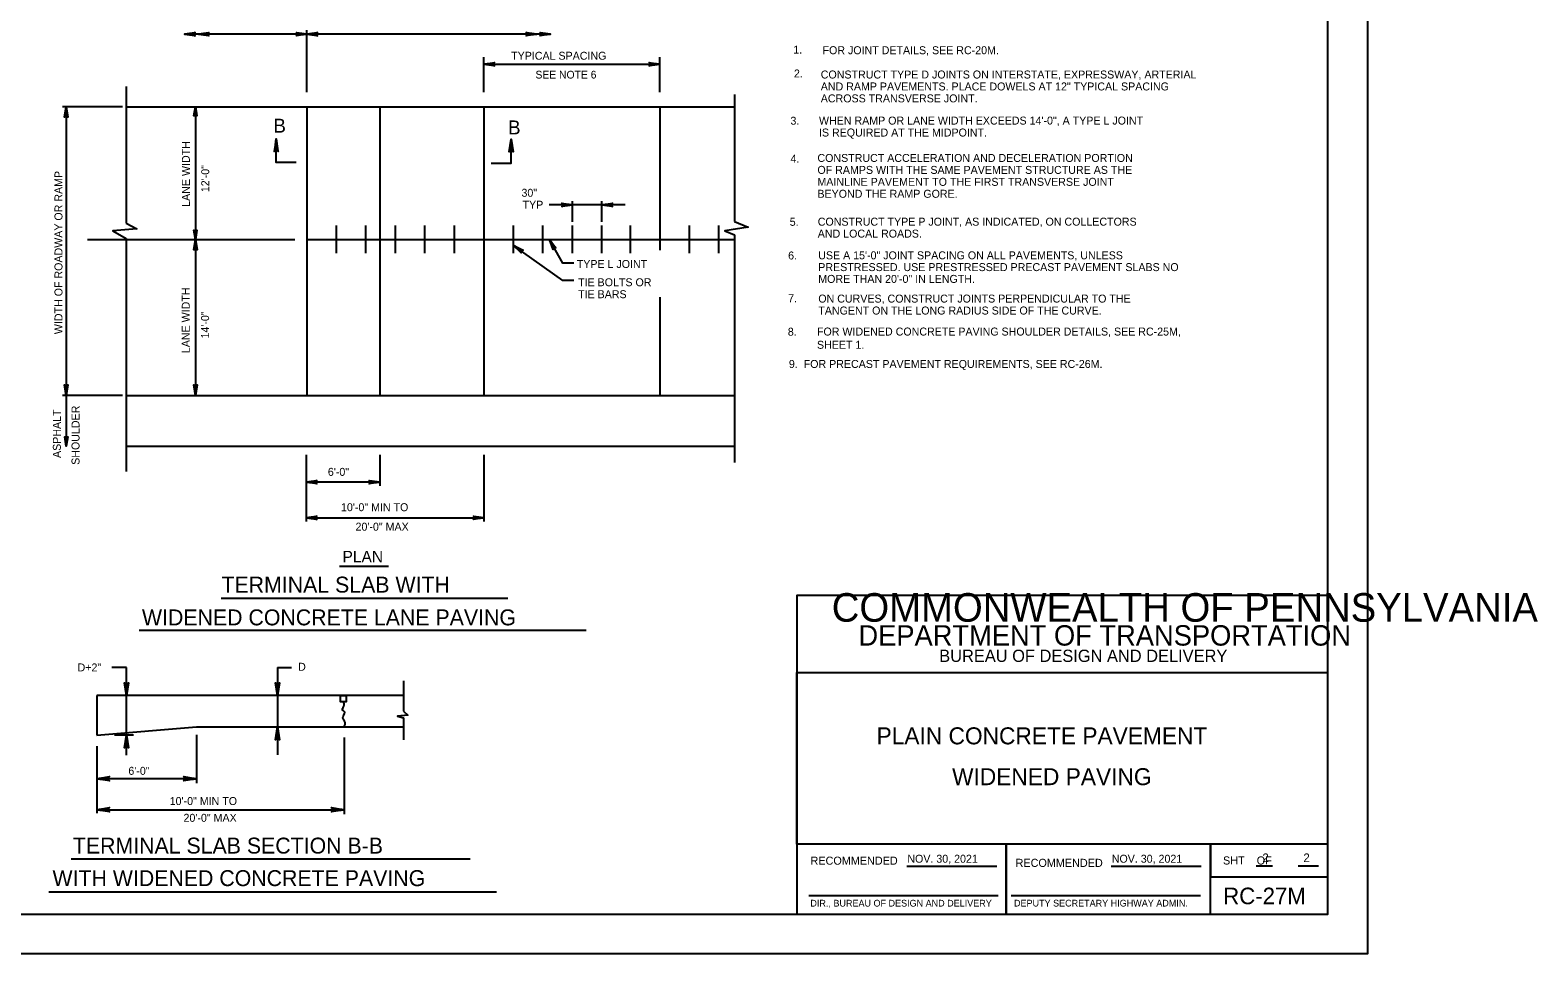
# Model space of a CAD drawing. Extents: x 637877 to 639321, y 297902 to 299090.
# Drawn here: x 638753 to 639321, y 297902 to 298250 of the extents above; entities that cross this region are included whole.
import ezdxf

# ---------------------------------------------------------------- set-up
doc = ezdxf.new("R2010")
doc.units = 0
for name, color, linetype in [('1', 7, 'Continuous'), ('2', 7, 'Continuous'), ('3', 7, 'Continuous'), ('PLT-BNDY', 7, 'Continuous')]:
    doc.layers.add(name, color=color, linetype=linetype)

msp = doc.modelspace()

# ---------------------------------------------------------------- linework, layer by layer
at = {"layer": '1'}
for p, q in [((639082.98, 297934.56), (639116.87, 297934.56)), ((639159.98, 297934.56), (639193.85, 297934.56)), ((639214.52, 297934.78), (639220.66, 297934.78)), ((639230.33, 297934.78), (639237.98, 297934.78)), ((639046.06, 297923.52), (639117.31, 297923.52)), ((639122.23, 297923.52), (639193.57, 297923.52))]:
    msp.add_line(p, q, dxfattribs=at)
for points in [[(639241.51, 297916.57), (639241.51, 298480.57), (638455.51, 298480.57), (638455.51, 297916.57), (639241.51, 297916.57), (639241.51, 297942.93), (639041.51, 297942.93), (639041.51, 298007.61), (639241.51, 298007.61), (639241.51, 298036.57), (639041.51, 298036.57), (639041.51, 297916.57), (639120.32, 297916.57), (639120.32, 297942.93), (639120.32, 297916.57), (639197.32, 297916.57), (639197.32, 297942.93), (639197.32, 297930.61), (639241.51, 297930.61)], [(638814.58, 298217.46), (638814.82, 298217.58), (638815, 298220.77), (638814.58, 298217.46), (638814.44, 298217.29), (638815, 298220.77), (638815.16, 298217.58), (638815.39, 298217.47), (638815, 298220.77), (638815.55, 298217.29), (638815.39, 298217.47)], [(638815.41, 298174.08), (638815.17, 298173.96), (638815, 298170.77), (638815.41, 298174.08), (638815.56, 298174.25), (638815, 298170.77), (638814.84, 298173.96), (638814.6, 298174.07), (638815, 298170.77), (638814.45, 298174.25), (638814.6, 298174.07)], [(638766.76, 298096.15), (638766.52, 298096.03), (638766.35, 298092.84), (638766.76, 298096.15), (638766.91, 298096.32), (638766.35, 298092.84), (638766.19, 298096.02), (638765.95, 298096.14), (638766.35, 298092.84), (638765.79, 298096.32), (638765.95, 298096.14)]]:
    msp.add_lwpolyline(points, dxfattribs=at)
msp.add_lwpolyline([(638869.69, 297998.93), (638871.78, 297998.93), (638871.78, 297996.49), (638869.69, 297996.49)], close=True, dxfattribs=at)
msp.add_spline([(638870.97, 297987.06), (638871.38, 297988.78), (638870.47, 297990.44), (638871.21, 297992.59), (638870.39, 297993.58), (638871.05, 297995.4), (638870.72, 297996.48)], degree=3, dxfattribs=at)
at = {"layer": '2'}
for p, q in [((638857, 298226.22), (638857, 298249.58)), ((638857, 298226.22), (638857, 298249.58)), ((638857, 298248.12), (638810.91, 298248.12)), ((638857, 298248.12), (638840.89, 298248.12)), ((638948.76, 298248.12), (638857, 298248.12)), ((638897.71, 298248.12), (638857, 298248.12)), ((638923.66, 298226.22), (638923.66, 298239.44)), ((638989.94, 298226.22), (638989.94, 298239.44)), ((638923.66, 298236.75), (638989.94, 298236.75)), ((638788.94, 298228.42), (638788.94, 298176.85)), ((638787.48, 298220.77), (638764.89, 298220.77)), ((638766.35, 298220.77), (638766.35, 298096.37)), ((638788.94, 298220.77), (639018.1, 298220.77)), ((638815, 298220.77), (638815, 298170.77)), ((638855.68, 298220.77), (638918.21, 298220.77)), ((638857, 298220.95), (638857, 298111.95)), ((638884.4, 298220.95), (638884.4, 298111.95)), ((638923.66, 298220.95), (638923.66, 298111.95)), ((638989.94, 298220.95), (638989.94, 298166.71)), ((639018.1, 298225.37), (639018.1, 298177.47)), ((638968.1, 298183.75), (638948.24, 298183.75)), ((638956.99, 298177.44), (638956.99, 298185.21)), ((638968.1, 298177.44), (638968.1, 298185.21)), ((638976.85, 298183.75), (638968.1, 298183.75)), ((638774.4, 298170.77), (638852.49, 298170.77)), ((638788.94, 298171.05), (638788.94, 298083.37)), ((638815, 298170.77), (638815, 298111.95)), ((638815, 298170.77), (638815, 298170.77)), ((638857, 298170.77), (639017.72, 298170.77)), ((638868.11, 298170.77), (638868.11, 298170.77)), ((638923.66, 298170.77), (638923.66, 298170.77)), ((639018.1, 298172.44), (639018.1, 298086.68)), ((638989.94, 298148.95), (638989.94, 298111.95)), ((638787.48, 298111.95), (638764.89, 298111.95)), ((638788.94, 298111.95), (639018.1, 298111.95)), ((638788.94, 298092.84), (639018.1, 298092.84)), ((638790.4, 298092.84), (638801.81, 298092.84)), ((638856.72, 298089.61), (638856.72, 298077.89)), ((638856.72, 298089.61), (638856.72, 298064.44)), ((638884.4, 298089.61), (638884.4, 298077.89)), ((638923.66, 298089.61), (638923.66, 298064.44)), ((638884.4, 298079.35), (638856.72, 298079.35)), ((638856.72, 298065.9), (638923.66, 298065.9)), ((638789.06, 298009.42), (638783.45, 298009.42)), ((638789.06, 297983.92), (638789.06, 298009.42)), ((638845.93, 298009.42), (638845.93, 297998.92)), ((638893.36, 298004.45), (638893.36, 297992.97)), ((638870.84, 297998.92), (638777.84, 297998.92)), ((638777.84, 297998.92), (638777.84, 297983.92)), ((638893.36, 297998.92), (638870.84, 297998.92)), ((638777.84, 297983.92), (638815.34, 297987.05)), ((638815.34, 297987.05), (638893.36, 297987.05)), ((638893.36, 297990.44), (638893.36, 297982.22)), ((638791.61, 297983.92), (638784.49, 297983.92)), ((638789.06, 297976.39), (638789.06, 297983.92)), ((638815.34, 297984.14), (638815.34, 297965.83)), ((638870.97, 297983.03), (638870.97, 297954.15)), ((638777.84, 297979.84), (638777.84, 297954.63)), ((638815.34, 297967.58), (638777.84, 297967.58)), ((638777.84, 297955.9), (638870.97, 297955.9))]:
    msp.add_line(p, q, dxfattribs=at)
for points in [[(638814.7, 298247.64), (638814.56, 298247.92), (638810.91, 298248.12), (638814.7, 298247.64), (638814.89, 298247.47), (638810.91, 298248.12), (638814.56, 298248.3), (638814.69, 298248.57), (638810.91, 298248.12), (638814.89, 298248.75), (638814.69, 298248.57)], [(638819.91, 298247.64), (638819.77, 298247.92), (638816.12, 298248.12), (638819.91, 298247.64), (638820.1, 298247.47), (638816.12, 298248.12), (638819.76, 298248.3), (638819.9, 298248.57), (638816.12, 298248.12), (638820.1, 298248.75), (638819.9, 298248.57)], [(638853.21, 298248.59), (638853.35, 298248.32), (638857, 298248.12), (638853.21, 298248.59), (638853.02, 298248.76), (638857, 298248.12), (638853.36, 298247.94), (638853.22, 298247.67), (638857, 298248.12), (638853.02, 298247.49), (638853.22, 298247.67)], [(638860.78, 298247.64), (638860.64, 298247.92), (638857, 298248.12), (638860.78, 298247.64), (638860.97, 298247.47), (638857, 298248.12), (638860.64, 298248.3), (638860.77, 298248.57), (638857, 298248.12), (638860.97, 298248.75), (638860.77, 298248.57)], [(638939.77, 298248.59), (638939.91, 298248.32), (638943.56, 298248.12), (638939.77, 298248.59), (638939.58, 298248.76), (638943.56, 298248.12), (638939.92, 298247.94), (638939.78, 298247.67), (638943.56, 298248.12), (638939.58, 298247.49), (638939.78, 298247.67)], [(638944.98, 298248.59), (638945.12, 298248.32), (638948.76, 298248.12), (638944.98, 298248.59), (638944.79, 298248.76), (638948.76, 298248.12), (638945.12, 298247.94), (638944.99, 298247.67), (638948.76, 298248.12), (638944.79, 298247.49), (638944.99, 298247.67)], [(638927.44, 298236.28), (638927.3, 298236.55), (638923.66, 298236.75), (638927.44, 298236.28), (638927.64, 298236.11), (638923.66, 298236.75), (638927.3, 298236.94), (638927.43, 298237.21), (638923.66, 298236.75), (638927.64, 298237.39), (638927.43, 298237.21)], [(638986.16, 298237.23), (638986.3, 298236.96), (638989.94, 298236.75), (638986.16, 298237.23), (638985.96, 298237.39), (638989.94, 298236.75), (638986.3, 298236.57), (638986.17, 298236.3), (638989.94, 298236.75), (638985.96, 298236.12), (638986.17, 298236.3)], [(638765.87, 298216.99), (638766.14, 298217.13), (638766.35, 298220.77), (638765.87, 298216.99), (638765.7, 298216.79), (638766.35, 298220.77), (638766.53, 298217.13), (638766.8, 298217), (638766.35, 298220.77), (638766.98, 298216.79), (638766.8, 298217)], [(638845.97, 298204.18), (638845.64, 298204.35), (638845.4, 298208.72), (638845.97, 298204.18), (638846.16, 298203.95), (638845.4, 298208.72), (638845.18, 298204.35), (638844.85, 298204.19), (638845.4, 298208.72), (638844.64, 298203.95), (638844.85, 298204.19)], [(638852.9, 298199.72), (638845.4, 298199.72), (638845.4, 298208.72)], [(638926.41, 298199.55), (638933.91, 298199.55), (638933.91, 298208.55)], [(638933.34, 298204), (638933.66, 298204.17), (638933.91, 298208.55), (638933.34, 298204), (638933.14, 298203.77), (638933.91, 298208.55), (638934.12, 298204.18), (638934.45, 298204.02), (638933.91, 298208.55), (638934.66, 298203.77), (638934.45, 298204.02)], [(638953.21, 298184.23), (638953.35, 298183.95), (638956.99, 298183.75), (638953.21, 298184.23), (638953.01, 298184.39), (638956.99, 298183.75), (638953.35, 298183.57), (638953.22, 298183.3), (638956.99, 298183.75), (638953.01, 298183.12), (638953.22, 298183.3)], [(638971.89, 298183.28), (638971.74, 298183.55), (638968.1, 298183.75), (638971.89, 298183.28), (638972.08, 298183.11), (638968.1, 298183.75), (638971.74, 298183.93), (638971.87, 298184.2), (638968.1, 298183.75), (638972.08, 298184.39), (638971.87, 298184.2)], [(638788.94, 298176.85), (638792.98, 298174.72), (638783.94, 298174), (638788.94, 298171.05)], [(638868.11, 298165.56), (638868.11, 298170.77), (638868.11, 298175.98)], [(638879.22, 298165.56), (638879.22, 298170.77), (638879.22, 298175.98)], [(638890.33, 298165.56), (638890.33, 298170.77), (638890.33, 298175.98)], [(638901.44, 298165.56), (638901.44, 298170.77), (638901.44, 298175.98)], [(638912.55, 298165.56), (638912.55, 298170.77), (638912.55, 298175.98)], [(638934.77, 298165.56), (638934.77, 298170.77), (638934.77, 298175.98)], [(638945.88, 298165.56), (638945.88, 298170.77), (638945.88, 298175.98)], [(638956.99, 298165.56), (638956.99, 298170.77), (638956.99, 298175.98)], [(638968.1, 298165.56), (638968.1, 298170.77), (638968.1, 298175.98)], [(638978.83, 298165.56), (638978.83, 298170.77), (638978.83, 298175.98)], [(639001.05, 298165.56), (639001.05, 298170.77), (639001.05, 298175.98)], [(639012.16, 298165.56), (639012.16, 298170.77), (639012.16, 298175.98)], [(639018.1, 298177.47), (639023.2, 298175.43), (639014.4, 298174), (639018.1, 298172.44)], [(638814.53, 298166.99), (638814.8, 298167.13), (638815, 298170.77), (638814.53, 298166.99), (638814.36, 298166.79), (638815, 298170.77), (638815.18, 298167.13), (638815.45, 298167), (638815, 298170.77), (638815.63, 298166.79), (638815.45, 298167)], [(638957.52, 298161.77), (638953.35, 298161.77), (638948.31, 298170.77)], [(638949.74, 298167.24), (638949.91, 298167.5), (638948.31, 298170.77), (638949.74, 298167.24), (638949.7, 298166.99), (638948.31, 298170.77), (638950.25, 298167.68), (638950.55, 298167.7), (638948.31, 298170.77), (638950.8, 298167.61), (638950.55, 298167.7)], [(638957.52, 298155.26), (638953.35, 298155.26), (638934.77, 298168.51)], [(638937.58, 298165.93), (638937.62, 298166.23), (638934.77, 298168.51), (638937.58, 298165.93), (638937.64, 298165.68), (638934.77, 298168.51), (638937.84, 298166.54), (638938.1, 298166.69), (638934.77, 298168.51), (638938.38, 298166.71), (638938.1, 298166.69)], [(638766.82, 298115.73), (638766.55, 298115.59), (638766.35, 298111.95), (638766.82, 298115.73), (638766.99, 298115.93), (638766.35, 298111.95), (638766.16, 298115.59), (638765.89, 298115.72), (638766.35, 298111.95), (638765.71, 298115.93), (638765.89, 298115.72)], [(638815.47, 298115.73), (638815.2, 298115.59), (638815, 298111.95), (638815.47, 298115.73), (638815.64, 298115.93), (638815, 298111.95), (638814.82, 298115.59), (638814.55, 298115.72), (638815, 298111.95), (638814.37, 298115.93), (638814.55, 298115.72)], [(638860.51, 298078.88), (638860.36, 298079.15), (638856.72, 298079.35), (638860.51, 298078.88), (638860.7, 298078.71), (638856.72, 298079.35), (638860.36, 298079.53), (638860.49, 298079.8), (638856.72, 298079.35), (638860.7, 298079.98), (638860.49, 298079.8)], [(638880.62, 298079.83), (638880.76, 298079.55), (638884.4, 298079.35), (638880.62, 298079.83), (638880.42, 298079.99), (638884.4, 298079.35), (638880.76, 298079.17), (638880.63, 298078.9), (638884.4, 298079.35), (638880.42, 298078.72), (638880.63, 298078.9)], [(638860.51, 298065.42), (638860.36, 298065.69), (638856.72, 298065.9), (638860.51, 298065.42), (638860.7, 298065.25), (638856.72, 298065.9), (638860.36, 298066.07), (638860.49, 298066.35), (638856.72, 298065.9), (638860.7, 298066.53), (638860.49, 298066.35)], [(638919.88, 298066.37), (638920.02, 298066.1), (638923.66, 298065.9), (638919.88, 298066.37), (638919.68, 298066.54), (638923.66, 298065.9), (638920.02, 298065.71), (638919.89, 298065.44), (638923.66, 298065.9), (638919.68, 298065.26), (638919.89, 298065.44)], [(638845.93, 298009.42), (638851.18, 298009.42)], [(638789.63, 298003.46), (638789.31, 298003.29), (638789.06, 297998.92), (638789.63, 298003.46), (638789.83, 298003.69), (638789.06, 297998.92), (638788.85, 298003.29), (638788.52, 298003.45), (638789.06, 297998.92), (638788.31, 298003.69), (638788.52, 298003.45)], [(638846.5, 298003.46), (638846.17, 298003.29), (638845.93, 297998.92), (638846.5, 298003.46), (638846.7, 298003.69), (638845.93, 297998.92), (638845.71, 298003.29), (638845.39, 298003.45), (638845.93, 297998.92), (638845.17, 298003.69), (638845.39, 298003.45)], [(638845.93, 297998.92), (638845.93, 297976.55)], [(638893.36, 297992.97), (638895.04, 297991.54), (638891.14, 297991.1), (638893.36, 297990.44)], [(638845.36, 297982.5), (638845.69, 297982.67), (638845.93, 297987.05), (638845.36, 297982.5), (638845.16, 297982.27), (638845.93, 297987.05), (638846.14, 297982.68), (638846.47, 297982.52), (638845.93, 297987.05), (638846.69, 297982.27), (638846.47, 297982.52)], [(638788.49, 297979.38), (638788.82, 297979.55), (638789.06, 297983.92), (638788.49, 297979.38), (638788.29, 297979.15), (638789.06, 297983.92), (638789.28, 297979.55), (638789.61, 297979.39), (638789.06, 297983.92), (638789.82, 297979.15), (638789.61, 297979.39)], [(638782.38, 297967.01), (638782.21, 297967.34), (638777.84, 297967.58), (638782.38, 297967.01), (638782.61, 297966.81), (638777.84, 297967.58), (638782.21, 297967.8), (638782.37, 297968.12), (638777.84, 297967.58), (638782.61, 297968.34), (638782.37, 297968.12)], [(638810.8, 297968.15), (638810.97, 297967.82), (638815.34, 297967.58), (638810.8, 297968.15), (638810.57, 297968.35), (638815.34, 297967.58), (638810.97, 297967.37), (638810.81, 297967.04), (638815.34, 297967.58), (638810.57, 297966.82), (638810.81, 297967.04)], [(638782.38, 297955.33), (638782.21, 297955.66), (638777.84, 297955.9), (638782.38, 297955.33), (638782.61, 297955.13), (638777.84, 297955.9), (638782.21, 297956.12), (638782.37, 297956.44), (638777.84, 297955.9), (638782.61, 297956.66), (638782.37, 297956.44)], [(638866.43, 297956.47), (638866.6, 297956.14), (638870.97, 297955.9), (638866.43, 297956.47), (638866.2, 297956.67), (638870.97, 297955.9), (638866.6, 297955.68), (638866.44, 297955.36), (638870.97, 297955.9), (638866.2, 297955.14), (638866.44, 297955.36)]]:
    msp.add_lwpolyline(points, dxfattribs=at)
at = {"layer": '3'}
for p, q in [((638869.28, 298047.6), (638887.74, 298047.6)), ((638824.71, 298035.63), (638932.62, 298035.63)), ((638793.86, 298023.59), (638962.21, 298023.59)), ((638768.23, 297937.37), (638918.47, 297937.37)), ((638759.78, 297924.97), (638928.4, 297924.97))]:
    msp.add_line(p, q, dxfattribs=at)
at = {"layer": 'PLT-BNDY'}
msp.add_lwpolyline([(638415.51, 298495.57), (639256.51, 298495.57), (639256.51, 297901.57), (638415.51, 297901.57)], close=True, dxfattribs=at)

# ---------------------------------------------------------------- texts
at = {"layer": '1'}
for s, height, p in [('COMMONWEALTH OF PENNSYLVANIA', 10.7834, (639054.67, 298026.71)), ('DEPARTMENT OF TRANSPORTATION', 7.6843, (639064.73, 298017.72)), ('BUREAU OF DESIGN AND DELIVERY', 4.6221, (639095.16, 298011.56)), ('PLAIN CONCRETE PAVEMENT', 6.4, (639071.55, 297980.52)), ('WIDENED PAVING', 6.4, (639100, 297965.13)), ('RECOMMENDED', 3.048, (639046.68, 297935.16)), ('NOV. 30, 2021', 3, (639083.15, 297935.91)), ('RECOMMENDED', 3.048, (639123.92, 297934.33)), ('NOV. 30, 2021', 3, (639160.15, 297935.91)), ('SHT    OF', 3.048, (639202.06, 297935.24)), ('2', 3.25, (639216.89, 297936.14)), ('2', 3.25, (639232.32, 297936.14)), ('RC-27M', 6.25, (639202.12, 297920.27)), ('DEPUTY SECRETARY HIGHWAY ADMIN.', 2.54, (639123.32, 297919.41))]:
    msp.add_text(s, height=height, dxfattribs=at).set_placement(p)
msp.add_text('DIR., BUREAU OF DESIGN AND DELIVERY', height=2.54, rotation=360, dxfattribs=at).set_placement((639046.63, 297919.39))
at = {"layer": '2'}
for s, height, p in [('CONSTRUCT TYPE D JOINTS ON INTERSTATE, EXPRESSWAY, ARTERIAL', 2.9995, (639050.54, 298231.4)), ('AND RAMP PAVEMENTS. PLACE DOWELS AT 12" TYPICAL SPACING', 2.9995, (639050.54, 298226.9)), ('ACROSS TRANSVERSE JOINT.', 2.9995, (639050.54, 298222.4)), ('30"', 3, (638937.8, 298186.84)), ('TYP', 3, (638938.22, 298182.34)), ('AND LOCAL ROADS. ', 2.9995, (639049.4, 298171.45)), ('CONSTRUCT TYPE P JOINT, AS INDICATED, ON COLLECTORS', 2.9995, (639049.4, 298175.95)), ('USE A 15\'-0" JOINT SPACING ON ALL PAVEMENTS, UNLESS ', 2.9995, (639049.59, 298163.27)), ('PRESTRESSED. USE PRESTRESSED PRECAST PAVEMENT SLABS NO ', 2.9995, (639049.59, 298158.83)), ('MORE THAN 20\'-0" IN LENGTH.  ', 2.9995, (639049.59, 298154.39)), ('7.', 3, (639038.24, 298147.1)), ('9.  FOR PRECAST PAVEMENT REQUIREMENTS, SEE RC-26M.', 2.9995, (639038.53, 298122.34))]:
    msp.add_text(s, height=height, dxfattribs=at).set_placement(p)
at = {"layer": '3'}
for s, height, p in [('1.  ', 2.999, (639040.18, 298240.76)), ('FOR JOINT DETAILS, SEE RC-20M.', 2.9995, (639051.21, 298240.55)), ('TYPICAL SPACING', 2.9997, (638933.91, 298238.47)), ('SEE NOTE 6', 2.917, (638943.07, 298231.39)), ('2.  ', 2.999, (639040.43, 298231.78)), ('B', 5.25, (638844.39, 298210.99)), ('B', 5.25, (638932.78, 298210.34)), ('3.  ', 3, (639039.11, 298213.98)), ('WHEN RAMP OR LANE WIDTH EXCEEDS 14\'-0", A TYPE L JOINT', 2.9995, (639049.86, 298214.04)), ('IS REQUIRED AT THE MIDPOINT.', 2.9995, (639049.86, 298209.54)), ('CONSTRUCT ACCELERATION AND DECELERATION PORTION', 2.9995, (639049.28, 298199.96)), ('4. ', 3, (639039.15, 298199.72)), ('OF RAMPS WITH THE SAME PAVEMENT STRUCTURE AS THE', 2.9995, (639049.28, 298195.46)), ('MAINLINE PAVEMENT TO THE FIRST TRANSVERSE JOINT', 2.9995, (639049.28, 298190.96)), ('BEYOND THE RAMP GORE.', 2.9995, (639049.28, 298186.46)), ('5.  ', 3, (639038.85, 298175.9)), ('6.  ', 3, (639038.25, 298163.21)), ('TYPE L JOINT', 2.9997, (638958.63, 298160.01)), ('TIE BOLTS OR', 2.9997, (638959.13, 298153.12)), ('TIE BARS', 3, (638959.13, 298148.62)), ('ON CURVES, CONSTRUCT JOINTS PERPENDICULAR TO THE', 2.9995, (639049.61, 298146.97)), ('TANGENT ON THE LONG RADIUS SIDE OF THE CURVE. ', 2.9995, (639049.61, 298142.47)), ('8.  ', 2.999, (639038.13, 298134.48)), ('FOR WIDENED CONCRETE PAVING SHOULDER DETAILS, SEE RC-25M,', 2.9995, (639049.11, 298134.55)), ('SHEET 1.', 2.999, (639049.11, 298129.56)), ('6\'-0"', 3, (638864.88, 298081.68)), ('10\'-0" MIN TO', 2.9997, (638869.83, 298068.36)), ('20\'-0" MAX', 3, (638875.3, 298061.02)), ('PLAN', 4.375, (638870.39, 298049.05)), ('TERMINAL SLAB WITH', 6, (638824.8, 298037.69)), ('WIDENED CONCRETE LANE PAVING', 6, (638794.85, 298025.35)), ('D+2"', 3, (638770.59, 298007.99)), ('D', 3, (638853.67, 298008.23)), ('6\'-0"', 3, (638789.73, 297969.03)), ('10\'-0" MIN TO', 2.9998, (638805.3, 297957.65)), ('20\'-0" MAX', 3, (638810.51, 297951.33)), ('TERMINAL SLAB SECTION B-B', 6, (638768.83, 297939.36)), ('WITH WIDENED CONCRETE PAVING', 6, (638761.15, 297927.1))]:
    msp.add_text(s, height=height, dxfattribs=at).set_placement(p)
for s, height, p in [('LANE WIDTH', 3, (638812.9, 298183.06)), ('12\'-0"', 3, (638820.19, 298188.57)), ('WIDTH OF ROADWAY OR RAMP', 2.9997, (638764.91, 298135.07)), ('LANE WIDTH', 3, (638812.85, 298127.92)), ('14\'-0"', 3, (638820.13, 298133.43)), ('ASPHALT', 3, (638764.3, 298088.42)), ('SHOULDER', 3, (638771.33, 298085.84))]:
    msp.add_text(s, height=height, rotation=90, dxfattribs=at).set_placement(p)

doc.saveas('drawing.dxf')
